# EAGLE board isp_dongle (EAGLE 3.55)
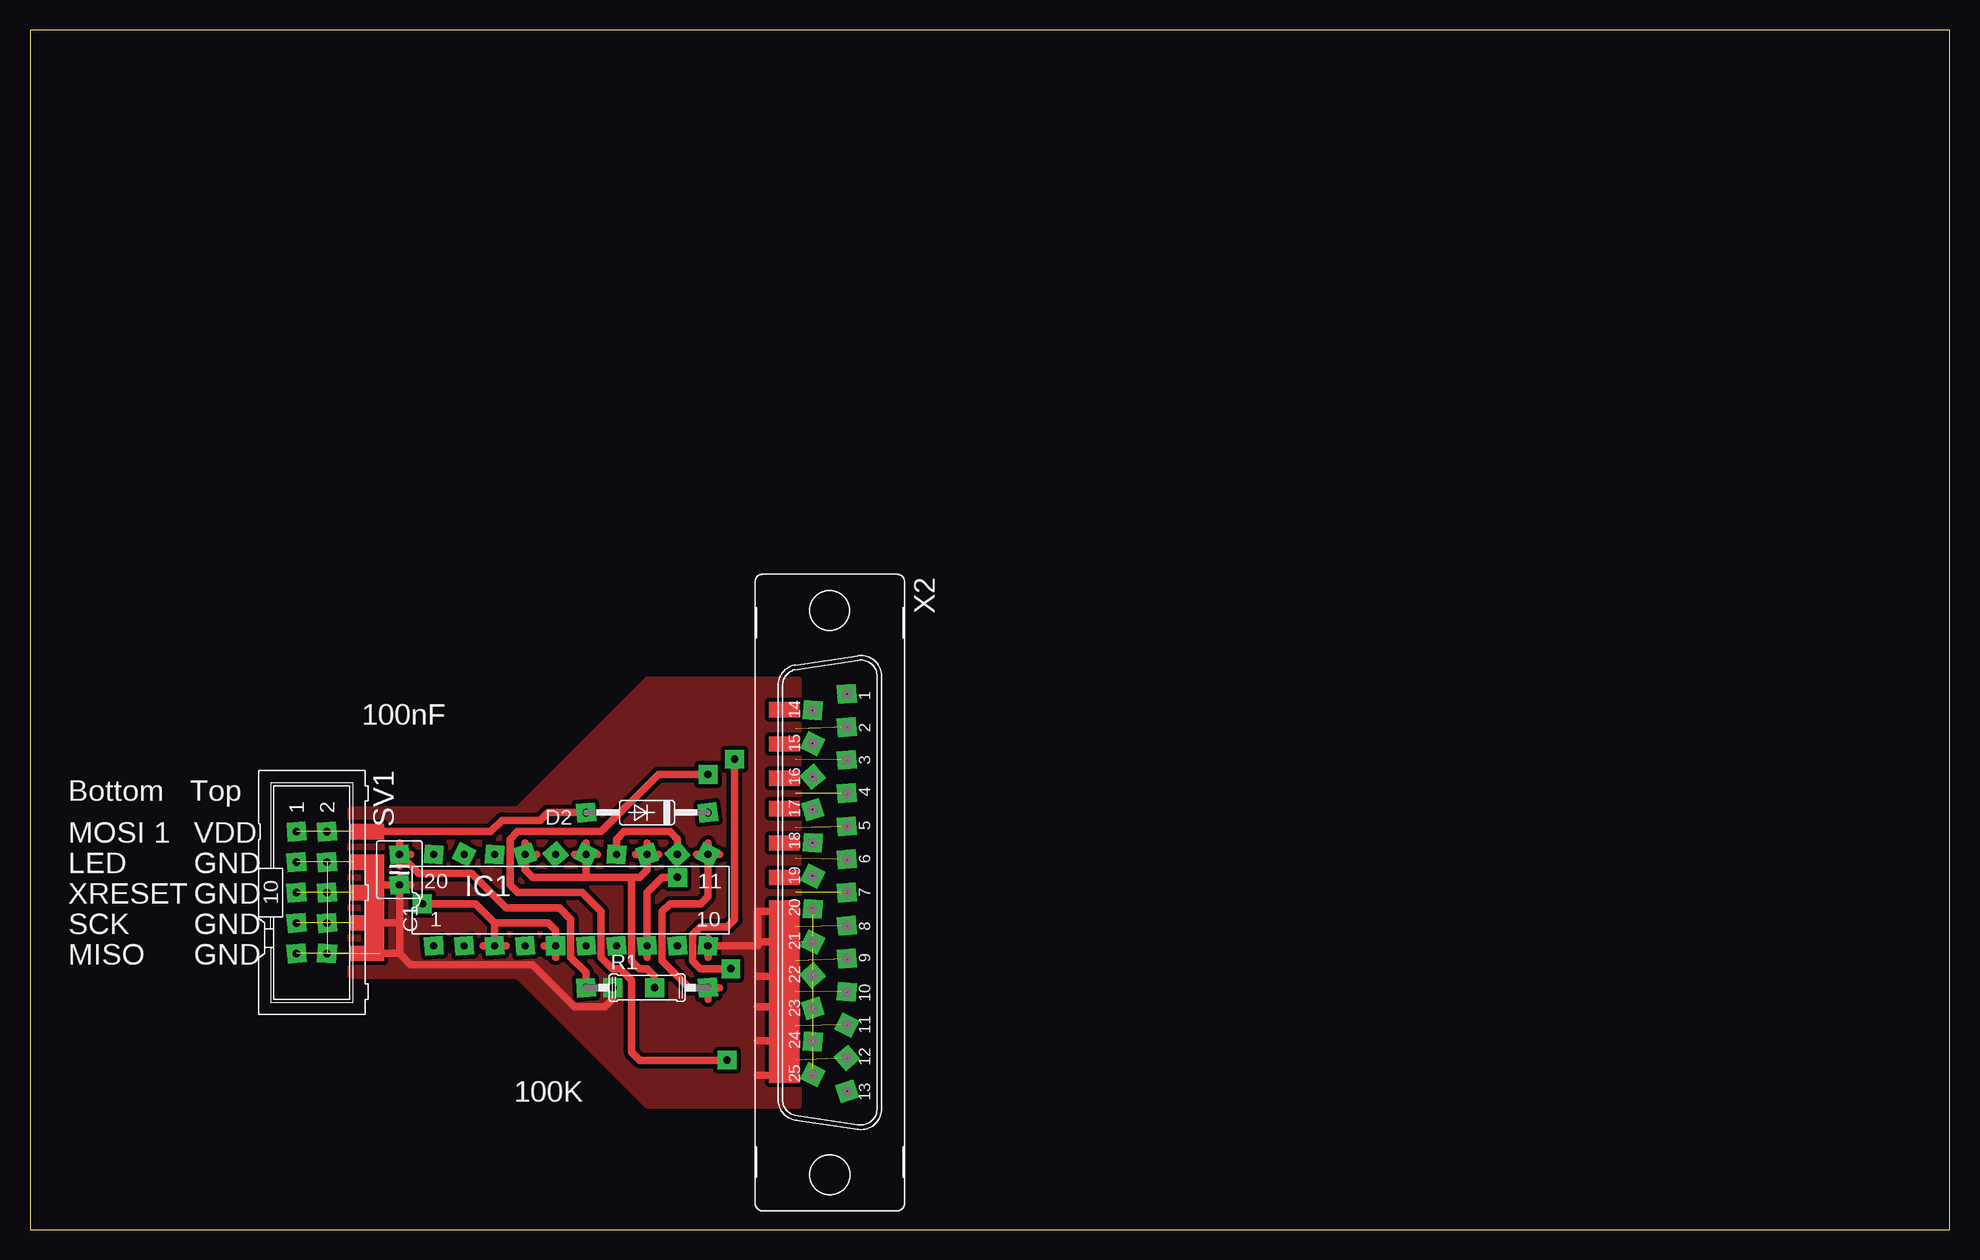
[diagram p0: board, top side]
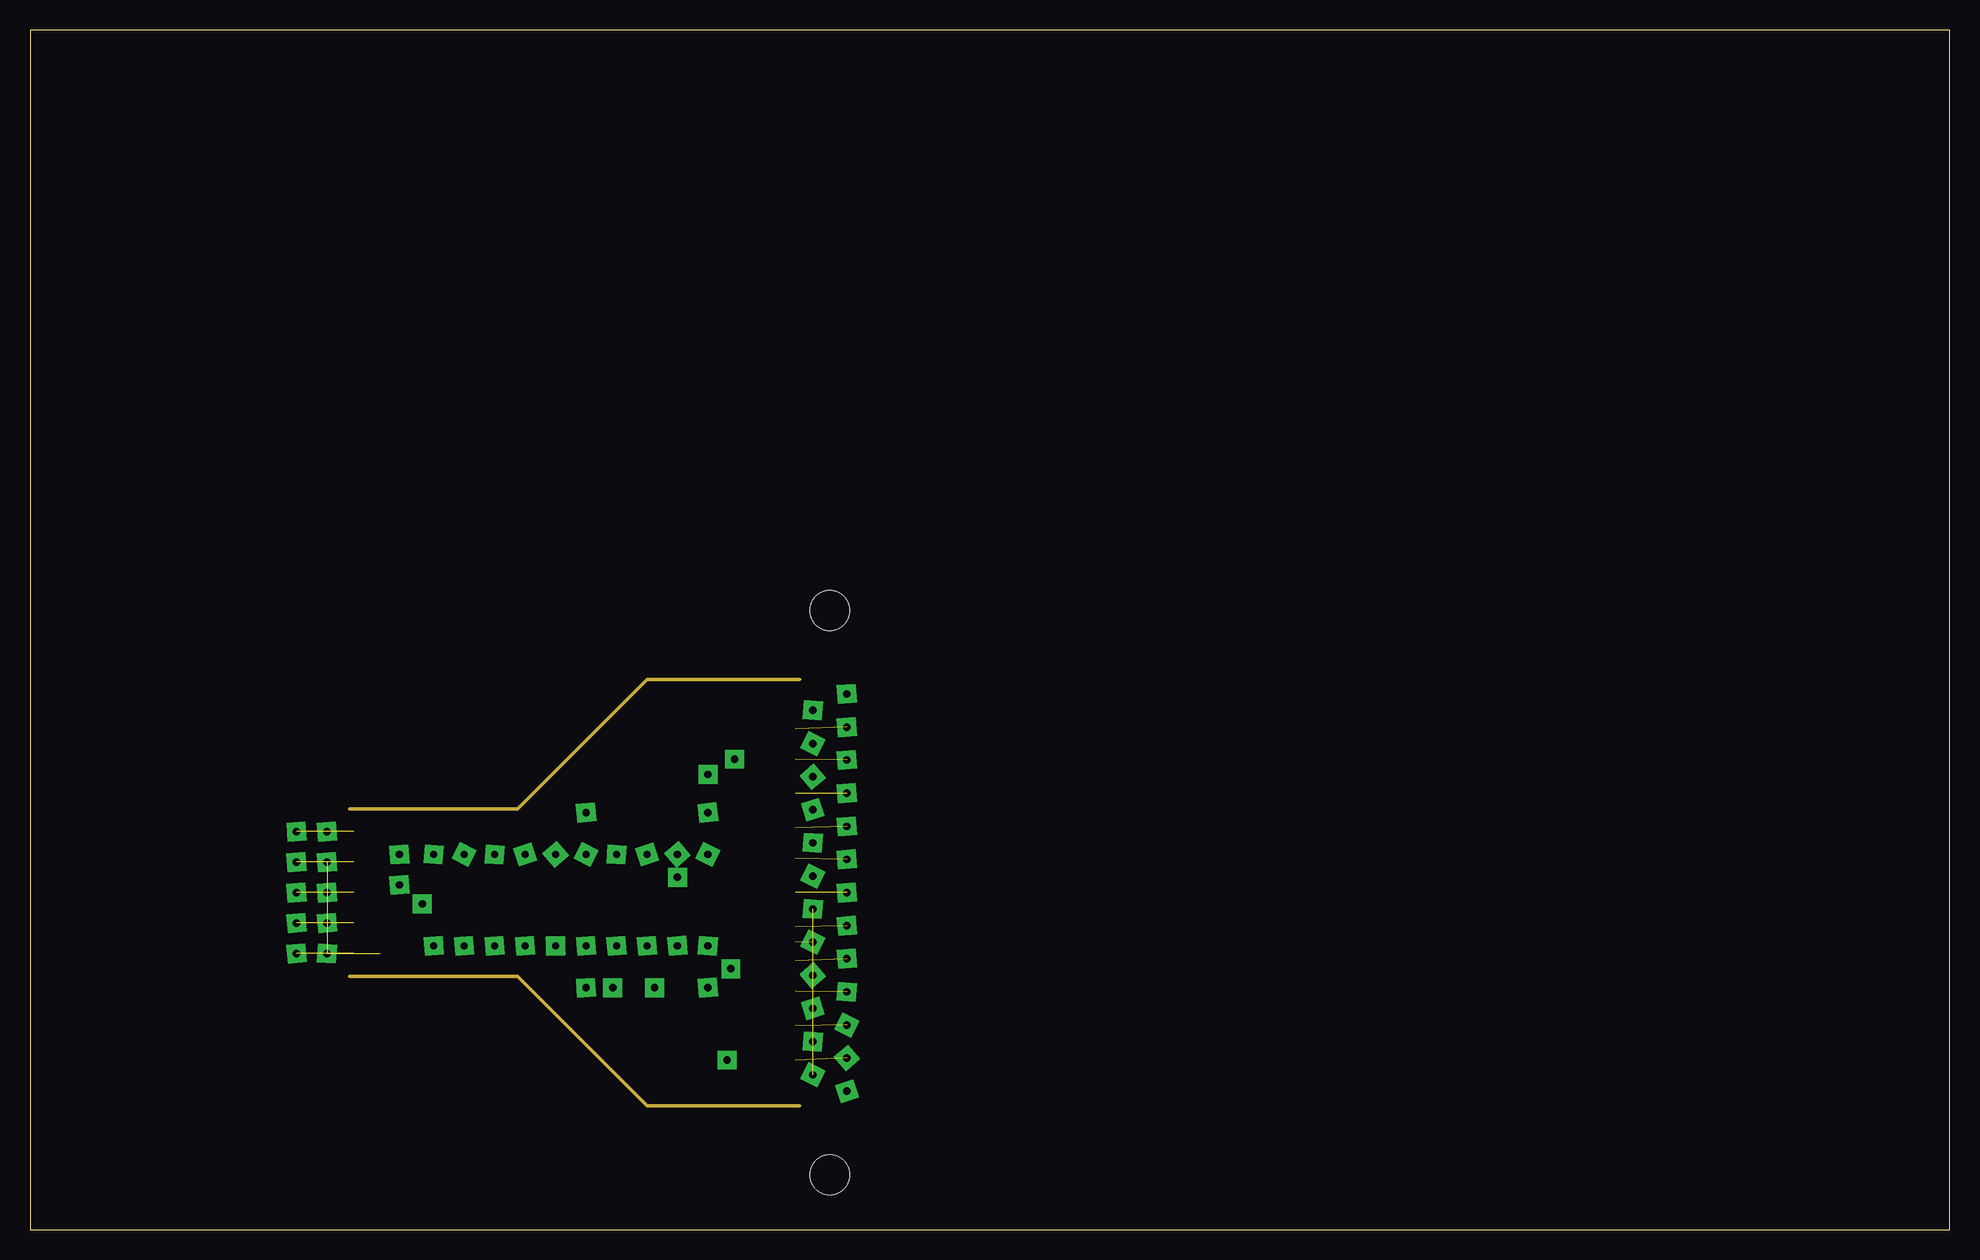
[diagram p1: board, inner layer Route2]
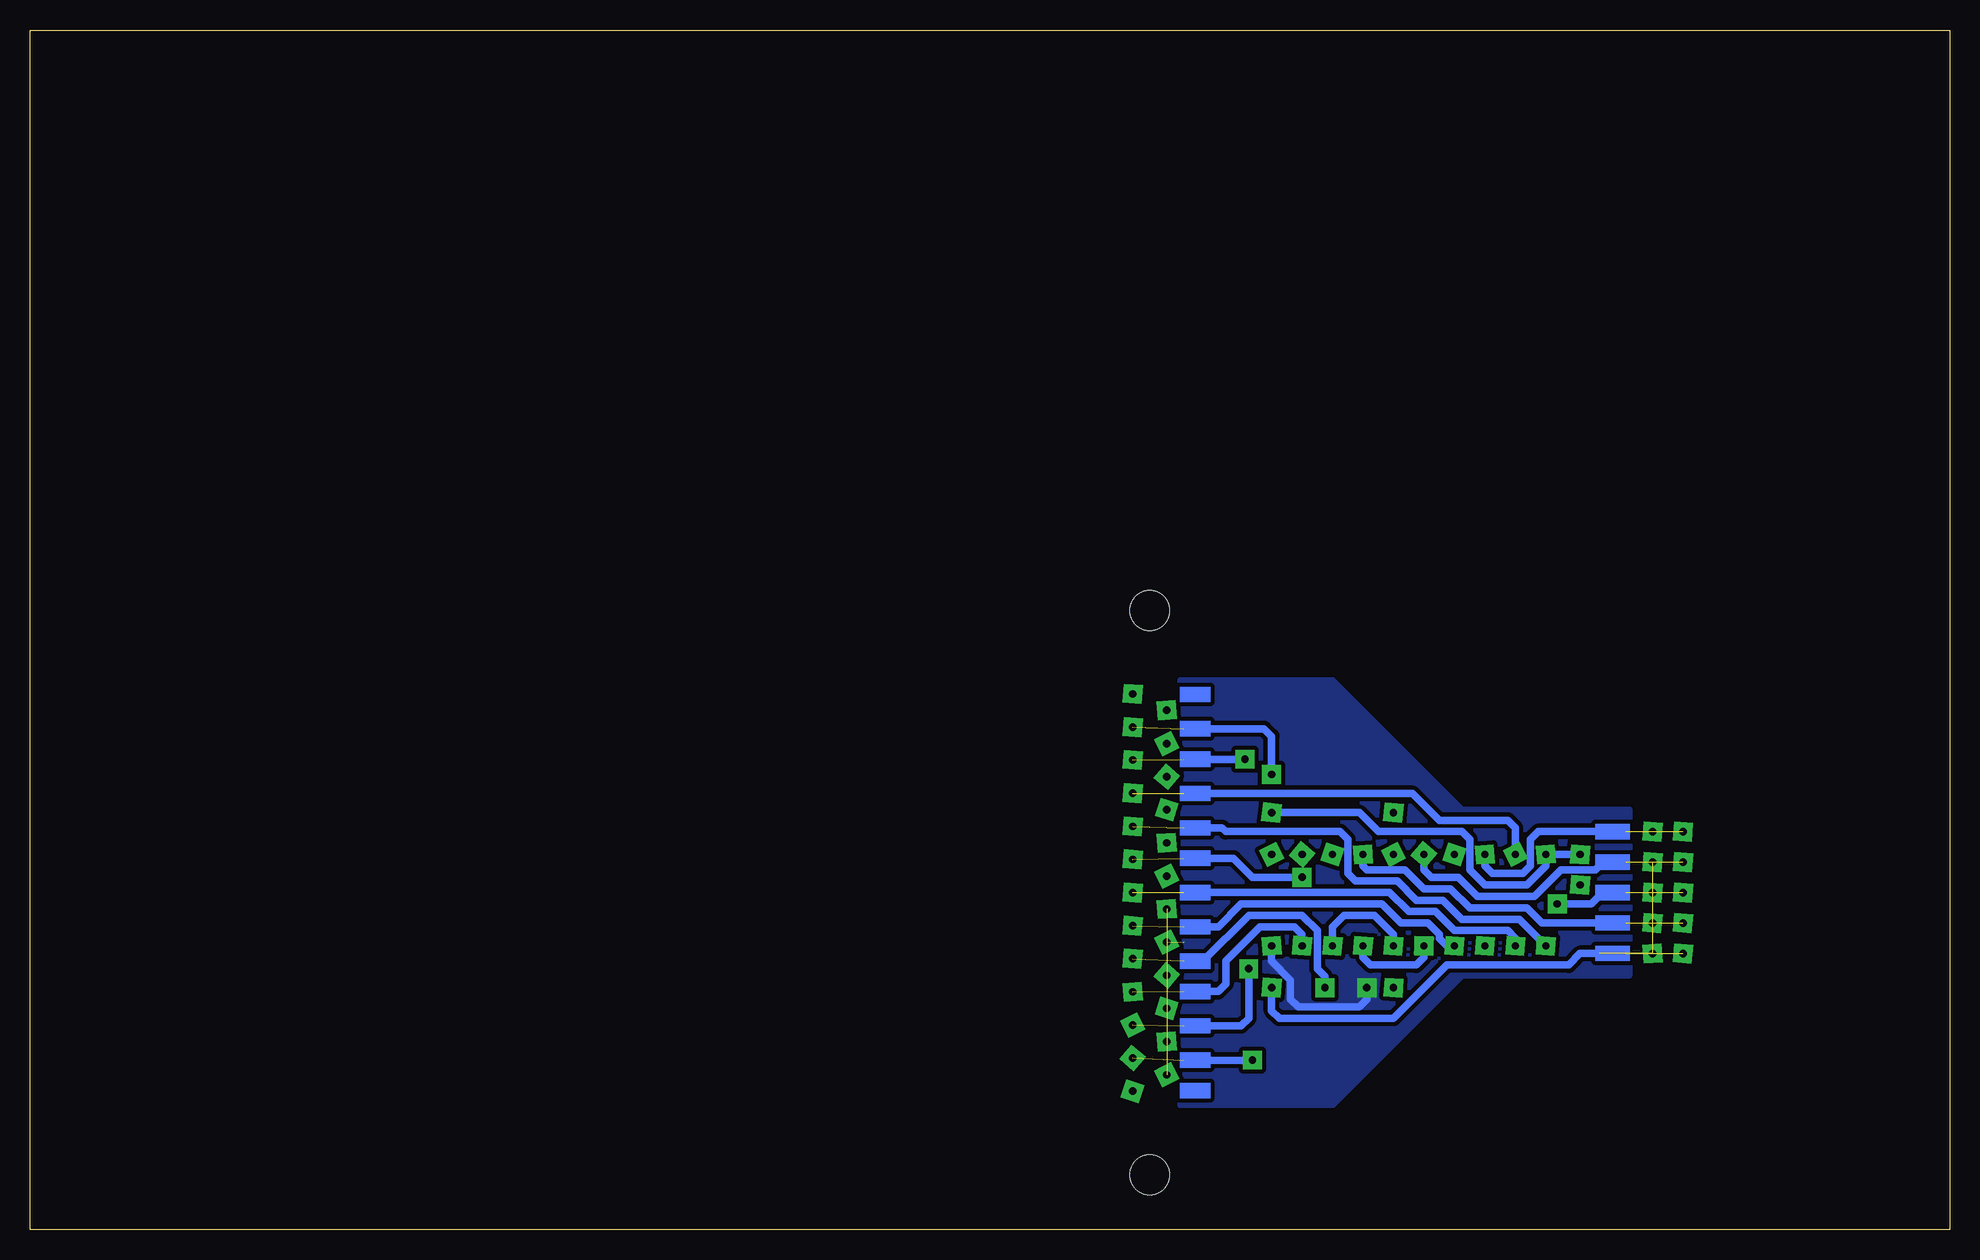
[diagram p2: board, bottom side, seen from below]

Size 160 x 100 mm. Coordinates in mm from the lower left corner, seen from the top.
Outline: 0,0 160,0 160,100 0,100 0,0
Copper layers used: Top, Route2, Bottom

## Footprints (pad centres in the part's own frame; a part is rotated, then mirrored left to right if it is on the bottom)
,5-4 = drill 0.61 pad 1.575 square:  -1.27,0;  1.27,0
35-10 = drill 0.61 pad 1.575 square:  -5.08,0;  5.08,0
L20 = drill 0.61 pad 1.575 square:  -11.43,-3.81;  -8.89,-3.81;  -6.35,-3.81;  -3.81,-3.81;  -1.27,-3.81;  1.27,-3.81;  3.81,-3.81;  6.35,-3.81;  8.89,-3.81;  11.43,-3.81;  11.43,3.81;  8.89,3.81;  6.35,3.81;  3.81,3.81;  1.27,3.81;  -1.27,3.81;  -3.81,3.81;  -6.35,3.81;  -8.89,3.81;  -11.43,3.81
07/10 = drill 0.61 pad 1.575 square:  -5.08,0;  5.08,0
10 = drill 0.61 pad 1.575 square:  -5.08,-1.27;  -5.08,1.27;  -2.54,-1.27;  -2.54,1.27;  0,-1.27;  0,1.27;  2.54,-1.27;  2.54,1.27;  5.08,-1.27;  5.08,1.27
5V = drill 0.61 pad 1.575 square:  16.561,1.422;  13.792,1.422;  11.049,1.422;  8.28,1.422;  5.512,1.422;  2.769,1.422;  0,1.422;  -2.769,1.422;  -5.512,1.422;  -8.28,1.422;  -11.049,1.422;  -13.792,1.422;  -16.561,1.422;  15.189,-1.422;  12.421,-1.422;  9.652,-1.422;  6.909,-1.422;  4.14,-1.422;  1.372,-1.422;  -1.372,-1.422;  -4.14,-1.422;  -6.909,-1.422;  -9.652,-1.422;  -12.421,-1.422;  -15.189,-1.422 | hole 3.302: 23.52,0; -23.52,0

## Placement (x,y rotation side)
C1  100nF  [,5-4]  30.79,30 270 top
D2  1N4148  [35-10]  51.43,34.76 180 top
IC1  74244  [L20]  45.08,27.46 0 top
R1  100K  [07/10]  51.43,20.15 0 top
SV1  ML10  [10]  23.49,28.09 270 top
X2  M25V  [5V]  66.67,28.09 270 top

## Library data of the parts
C1 = CAP
D2 = DIODE
IC1 = 74XX
R1 = R
SV1 = CON-ML
X2 = SUBD-A

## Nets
GND: C1. IC1. SV1. X2.
LED: IC1. SV1.
MISO: IC1. R1. SV1.
MOSI: IC1. SV1.
N$1: X2.
N$2: X2.
N$3: IC1. X2.
N$4: IC1. X2.
N$5: IC1. X2.
N$6: IC1. X2.
N$8: IC1. X2.
N$9: IC1. X2.
N$10: IC1. X2.
RST: IC1. SV1.
SCK: IC1. SV1.
VCC: C1. D2. IC1. R1.
VDD: D2. SV1.

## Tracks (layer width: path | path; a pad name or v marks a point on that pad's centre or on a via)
GND  (via drill 0.61 pad 1.57)  (10 unrouted)
  Top 0.61: v48.57,20.15 48.57,19.2 47.94,18.57 45.4,18.57 41.91,22.06 31.74,22.06 30.79,23.01 | 30.79,23.01 30.79,25.55 | 30.79,25.55 C1. | 56.51,23.65 60.64,23.65 60.64,23.96 | 60.64,23.96 63.81,23.96 | C1. 31.74,28.73 | C1. 29.2,28.73 | 30.79,23.01 29.2,23.01 | 30.79,25.55 29.52,25.55 | 56.51,23.65 56.51,22.7 | 56.51,23.65 56.51,24.28 | C1. 30.79,29.36 | 60.64,23.96 60.64,26.5 61.91,26.5 | 60.64,21.11 61.91,21.11 | 60.64,18.57 61.91,18.57 | 60.64,15.71 61.91,15.71 | 60.64,12.85 61.91,12.85
  Bottom 0.61: 56.51,23.65 56.51,22.38 54.92,20.79 54.92,19.2 54.29,18.57 49.21,18.57 48.57,19.2 v48.57,20.15
  pour Bottom (isolate 0.356, no thermals): 64.13,45.87 51.43,45.87 40.64,35.08 26.66,35.08 26.66,21.11 40.64,21.11 51.43,10.31 64.13,10.31
  pour Top (isolate 0.356): 64.13,45.87 51.43,45.87 40.64,35.08 26.66,35.08 26.66,21.11 40.64,21.11 51.43,10.31 64.13,10.31
LED  (1 unrouted)
  Bottom 0.61: 43.81,31.27 43.81,30 43.18,29.36 40.95,29.36 39.37,27.77 34.6,27.77 32.38,30 29.52,30 28.89,30.63 26.98,30.63
MISO  (1 unrouted)
  Top 0.61: R1. 54.92,20.15 52.7,22.38 52.7,26.5 53.34,27.14 55.88,27.14 56.51,27.77 56.51,31.27 | R1. 57.46,20.15 | R1. 56.51,19.2 | 56.51,31.27 56.51,32.22 | 56.51,31.27 57.46,31.27
  Bottom 0.61: R1. 56.51,18.25 55.88,17.61 46.35,17.61 41.91,22.06 31.74,22.06 30.79,23.01 26.98,23.01
MOSI  (1 unrouted)
  Bottom 0.61: 38.73,31.27 38.73,30.31 38.1,29.68 35.55,29.68 34.92,30.31 34.92,32.54 34.29,33.17 26.98,33.17
N$1  (via drill 0.61 pad 1.57)  (2 unrouted)
  Top 0.61: v56.51,37.94 52.38,37.94 47.62,33.17 40.64,33.17 40,32.54 40,28.73 40.64,28.09 46.03,28.09 47.62,26.5 47.62,22.7 48.57,21.74 49.21,21.74 50.16,20.79 50.16,14.76 50.8,14.12 v58.1,14.12
  Bottom 0.61: v56.51,37.94 56.51,41.11 57.15,41.74 63.81,41.74 | v58.1,14.12 63.81,14.12
N$2  (via drill 0.61 pad 1.57)  (2 unrouted)
  Top 0.61: v58.41,21.74 55.88,21.74 55.24,22.38 55.24,24.6 55.88,25.23 58.1,25.23 58.73,25.87 v58.73,39.2
  Bottom 0.61: v58.41,21.74 58.41,17.61 59.05,16.98 63.81,16.98 | v58.73,39.2 63.81,39.2
N$3  (1 unrouted)
  Bottom 0.61: 36.19,31.27 36.19,33.49 36.83,34.12 42.54,34.12 44.76,36.35 63.81,36.35
N$4  (1 unrouted)
  Bottom 0.61: 41.27,23.65 41.91,23.65 42.54,24.28 42.54,24.6 43.49,25.55 45.72,25.55 47.3,27.14 59.05,27.14 60.96,25.23 63.81,25.23
N$5  (via drill 0.61 pad 1.57)  (1 unrouted)
  Top 0.61: v53.97,29.36 52.7,29.36 51.43,28.09 51.43,23.65
  Bottom 0.61: 51.43,23.65 51.43,25.23 50.48,26.19 47.94,26.19 46.35,24.6 46.35,23.65 | v53.97,29.36 58.1,29.36 59.69,30.95 63.81,30.95
N$6  (1 unrouted)
  Bottom 0.61: 36.19,23.65 36.19,24.28 36.83,24.92 41.27,24.92 42.86,26.5 45.08,26.5 46.67,28.09 63.81,28.09
N$7
  Route2 0.305: 64.13,45.87 51.43,45.87 40.64,35.08 26.66,35.08
N$8  (1 unrouted)
  Bottom 0.61: 63.81,33.49 60.64,33.49 60.32,33.17 50.8,33.17 50.16,32.54 50.16,29.68 49.53,29.04 46.03,29.04 44.45,27.46 42.22,27.46 40.64,25.87 35.87,25.87 33.65,23.65
N$9  (1 unrouted)
  Bottom 0.61: 53.97,23.65 53.97,24.6 54.61,25.23 57.46,25.23 60.32,22.38 60.32,20.47 60.96,19.84 63.81,19.84
N$10  (via drill 0.61 pad 1.57)  (1 unrouted)
  Top 0.61: 41.27,31.27 41.27,30 41.91,29.36 50.16,29.36 | 50.16,29.36 50.8,29.36 51.43,30 51.43,31.27 | v52.07,20.15 52.07,21.11 51.43,21.74 50.8,21.74 50.16,22.38 50.16,29.36 | 50.16,29.36 46.35,29.36 46.35,31.27 | 41.27,31.27 42.22,31.27 | 46.35,31.27 47.3,31.27 | 46.35,31.27 45.4,31.27 | 51.43,31.27 51.43,32.22 | 51.43,31.27 52.38,31.27 | 41.27,31.27 41.27,32.22 | 46.35,31.27 46.35,32.22 | 51.43,31.27 50.48,31.27
  Bottom 0.61: v52.07,20.15 52.07,21.11 52.7,21.74 52.7,24.92 53.97,26.19 58.41,26.19 62.23,22.38 63.81,22.38
N$11
  Route2 0.305: 64.13,10.31 51.43,10.31 40.64,21.11 26.66,21.11
N$12
  Top 0.61: 51.43,22.7 51.43,23.33
N$13
  Top 0.61: 56.19,31.27 55.56,31.27
RST  (via drill 0.61 pad 1.57)  (1 unrouted)
  Top 0.61: 38.73,25.55 43.18,25.55 43.81,24.92 v43.81,23.65 | 38.73,25.55 38.73,23.65 | v32.7,27.14 37.14,27.14 38.73,25.55 | 38.73,23.65 39.68,23.65 | 38.73,23.65 37.78,23.65 | v43.81,23.65 43.81,22.7 | v43.81,23.65 42.86,23.65
  Bottom 0.61: 26.98,28.09 28.89,28.09 29.84,27.14 v32.7,27.14 | 48.89,23.65 48.89,22.7 48.26,22.06 44.45,22.06 43.81,22.7 v43.81,23.65
SCK  (1 unrouted)
  Top 0.61: 48.89,31.27 48.89,32.54 49.53,33.17 53.34,33.17 53.97,32.54 53.97,31.27
  Bottom 0.61: 48.89,31.27 48.89,30.31 48.57,30 45.4,30 43.81,28.41 41.59,28.41 40,26.82 35.24,26.82 33.97,25.55 26.98,25.55
VCC
  Top 0.61: 46.35,20.15 46.35,21.42 45.08,22.7 45.08,25.87 44.13,26.82 39.68,26.82 36.83,29.68 32.38,29.68 30.79,31.27 | 30.79,31.27 30.79,32.22 | 30.79,31.27 31.74,31.27 | 30.79,30.31 30.79,31.27
  Bottom 0.61: 56.51,34.76 49.21,34.76 47.62,33.17 40.64,33.17 40,32.54 40,30 38.73,28.73 35.24,28.73 33.65,30.31 IC1. 30.79,31.27
VDD  (1 unrouted)
  Top 0.61: D2. 43.18,34.76 42.54,34.12 39.37,34.12 38.41,33.17 26.98,33.17
(copper drawn outside any net)
  shapes: Bottom area x18, Top area x16

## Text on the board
tNames: 100nF | Bottom | Top | MOSI 1 | VDD | LED | GND | XRESET | GND | SCK | GND | MISO | GND | 100K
